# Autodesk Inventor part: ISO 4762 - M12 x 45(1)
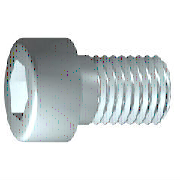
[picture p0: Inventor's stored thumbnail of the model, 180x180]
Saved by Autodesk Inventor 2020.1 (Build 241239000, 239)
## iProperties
Created: 2019-01
Part Number: ISO 4762 - M12 x 45(1)
Material: Edelstahl, 440C
Description: Innensechskantschraube
Document SubType Name: Modeling
Standard: ISO 4762
Designer: lutzd
Standard Revision: Fourth edition 2004-03-01
Standards Organization: ISO
Language: de-DE
Size Designation: M12 x 45
Categories: <MemberInstance><Categories><Category DisplayName="Verbindungselemente" InternalName="e4da775c-781d-43d5-af7c-5136215cf5a6" Mnemonic="FSTN"><Category DisplayNam
Mass: 57.9152 g
Surface Area: 30.588 cm^2
Volume: 7.47293 cm^3
Density: 7.75 g/cm^3
Appearance: Halbpoliert
IsCustomPart: 0
Author: lutzd
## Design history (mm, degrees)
body "Solid1"
sketch "Skizze1"
  geometry: L1 (-2.667, 0)-(45, 0); L2 (45, 0)-(45, 6); L3 (45, 6)-(4.375, 6); L4 (4.375, 6)-(3.301, 6); L5 (3.301, 6)-(0, 6); L6 (0, 6)-(0, 9); L7 (0, 9)-(-12, 9); L8 (-12, 9)-(-12, 5.774); L9 (-12, 5.774)-(-6, 5.774); L10 (-6, 5.774)-(-2.667, 0); L11 (-23.4, 0)-(56.4, 0) reference; L12 (0, -1.8)-(0, 10.8) reference; L13 (4.375, 6)-(0, 6)
  constraints: 22 end point, 6 parallel, 2 collinear, 2 perpendicular, 1 horizontal, 1 point on line
  dimensions: "d1" = 40.625 distance from line of L3.end L2 (= GEL); "d2" = 1.07364 distance of L4.end L3.end (computed from GAL); "d3" = 12 distance between parallel lines of L8 L6 (= KOH); "d4" = 6 distance of L8.end L9.end (= INTI); "d5" = 60 deg angle of L10 L1; "d6" = 12 diameter of L3 L1 (= GD); "d7" = 12 diameter of L5 L1 (= BDM); "d8" = 11.54701 diameter of L9 L1 (= 1.1547 x SW); "d9" = 18 diameter of L7 L1 (= KOD); "d26" = 45 distance between parallel lines of L12 L2 (= NLG)
workplane "Work Plane1"
fillet "Fillet2" dims "d30" = 0.1 (= R)
revolve "Körper" stored, may be unused: angle "d10" = 90 deg
sketch "Skizze2"
  geometry: L1 (0, -12.6)-(0, 12.6) reference; L2 (-12.6, 0)-(12.6, 0) reference; L3 (5.774, 0)-(2.887, -5); L4 (2.887, -5)-(-2.887, -5); L5 (-2.887, -5)-(-5.774, 0); L6 (-5.774, 0)-(-2.887, 5); L7 (-2.887, 5)-(2.887, 5); L8 (2.887, 5)-(5.774, 0); 2 further points
  constraints: 12 end point, 1 coincident, 1 horizontal alignment, 1 point on line, 12 other
extrude "Loch" join sketch "Skizze2" stored distance "d11" = 10; taper "d12" = 0 deg
fillet "Rundung1" dims "d17" = 1.2 (= RR)
feature "Gewinde" dims "d13" = 40.625 (= GEL), "d14" = 0
chamfer "Fase1" distance "d15" = 1.07354 (= -0.5 x SPD + 0.5 x GD); stored, may be unused: second distance "d16" = 1.07354 (= GUL), angle "d27" = 45 deg
other parameters: "GD" = 12 [user parameter; used in 2 equation terms], "NLG" = 45 [user parameter; used in 1 equation term], "GEL" = 40.625 [user parameter; used in 2 equation terms], "KOD" = 18 [user parameter; used in 1 equation term], "KOH" = 12 [user parameter; used in 1 equation term], "INTI" = 6 [user parameter; used in 1 equation term], "GAL" = 1.07354 (= 0.61345 x PTC) [user parameter; used in 1 equation term], "GUL" = 1.07354 (= 0.61345 x PTC) [user parameter; used in 1 equation term], "BDM" = 12 (= NND) [user parameter; used in 1 equation term], "RR" = 1.2 [user parameter; used in 1 equation term], "SPD" = 9.85293 (= NND - 1.2269 x PTC) [user parameter; used in 1 equation term], "d19" = 0, "d28" = 0, "d29" = 0, "R" = 0.1 [user parameter; used in 1 equation term], "TOA" = 30 deg [user parameter], "GD1" = 9.85293 (= THREADDIA - 1.2269 x PTC) [user parameter], "THREADDIA" = 12 [user parameter; used in 1 equation term], "FAWI" = 45 deg [user parameter], "TPU" = 5.71429 (computed from PTC) [user parameter], "PTC" = 1.75 [user parameter; used in 5 equation terms], "NND" = 12 [user parameter; used in 2 equation terms], "E0" = 11.55 (= 1.155 x SW) [user parameter]
